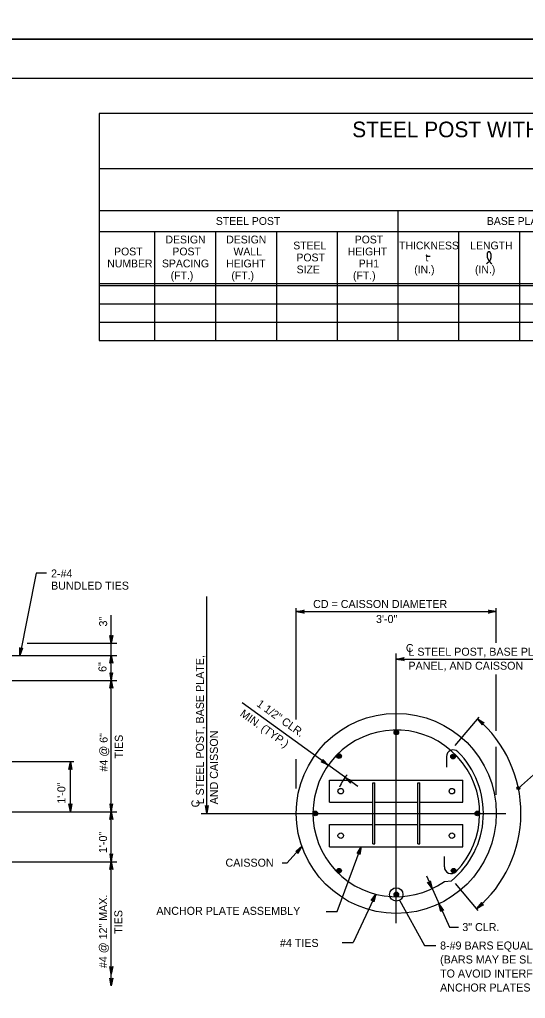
# Model space of a CAD drawing. Extents: x 3475 to 6558, y -3780 to 1166.
# Drawn here: x 4064.1 to 4258.3, y -390.6 to -14.8 of the extents above; entities that cross this region are included whole.
import ezdxf

# ---------------------------------------------------------------- set-up
doc = ezdxf.new("R2010")
doc.units = 0
for name, color, linetype in [('1', 7, 'Continuous'), ('2', 7, 'Continuous'), ('PLT-BNDY', 7, 'Continuous')]:
    doc.layers.add(name, color=color, linetype=linetype)

msp = doc.modelspace()

# ---------------------------------------------------------------- linework, layer by layer
at = {"layer": '1'}
for p, q in [((4094.64, -50.81), (4094.64, -138.01)), ((4574.64, -50.81), (4094.64, -50.81)), ((4574.64, -72.14), (4094.64, -72.14)), ((4094.64, -88.14), (4574.64, -88.14)), ((4094.64, -88.14), (4205.97, -88.14)), ((4209.3, -88.14), (4209.3, -138.01)), ((4094.64, -96.14), (4574.64, -96.14)), ((4115.97, -138.01), (4115.97, -96.14)), ((4139.3, -96.14), (4139.3, -138.01)), ((4162.64, -96.14), (4162.64, -138.01)), ((4185.97, -96.14), (4185.97, -138.01)), ((4232.64, -96.14), (4232.64, -138.01)), ((4255.97, -96.14), (4255.97, -138.01)), ((4220.17, -105.64), (4221.76, -105.64)), ((4094.64, -116.14), (4574.64, -116.14)), ((4094.64, -116.89), (4574.64, -116.89)), ((4094.64, -123.93), (4574.64, -123.93)), ((4094.64, -130.97), (4574.64, -130.97)), ((4094.64, -138.01), (4574.64, -138.01)), ((4070.42, -227.39), (4064.1, -258.93)), ((4074.37, -227.39), (4070.42, -227.39)), ((4135.94, -319.55), (4135.94, -236.27)), ((4099.26, -385.81), (4099.26, -243.47)), ((4170.3, -283.55), (4170.3, -240.78)), ((4170.3, -242.1), (4247.1, -242.1)), ((4247.1, -254.1), (4247.1, -240.78)), ((4067, -254.2), (4101.4, -254.2)), ((3993.38, -258.93), (4101.4, -258.93)), ((4208.7, -361.75), (4208.7, -258.14)), ((4208.7, -260.31), (4288.8, -260.31)), ((4247.1, -287.87), (4247.1, -266.24)), ((3993.38, -268.53), (4101.4, -268.53)), ((4193.88, -309.25), (4149.55, -277.14)), ((4240.44, -282.56), (4231.11, -293.43)), ((4247.1, -312.42), (4247.1, -294)), ((4084.88, -299.7), (3982.86, -299.7)), ((4083.55, -318.9), (4083.55, -299.7)), ((4170.3, -309.97), (4170.3, -298.78)), ((4227.94, -297.78), (4227.95, -301.81)), ((4184.02, -302.11), (4184.02, -302.11)), ((4184.02, -302.11), (4184.02, -302.11)), ((4184.02, -302.11), (4184.02, -302.11)), ((4263.68, -302.73), (4255.56, -309.87)), ((4183.1, -306.75), (4234.3, -306.75)), ((4183.1, -315.29), (4183.1, -306.75)), ((4199.65, -331.29), (4199.65, -307.82)), ((4199.65, -307.82), (4200.45, -307.82)), ((4200.45, -331.29), (4200.45, -307.82)), ((4216.96, -307.82), (4217.75, -307.82)), ((4216.96, -315.09), (4216.96, -307.82)), ((4217.75, -331.29), (4217.75, -307.82)), ((4234.3, -315.29), (4234.3, -306.75)), ((4183.1, -315.29), (4199.65, -315.29)), ((4200.45, -315.29), (4216.96, -315.29)), ((4216.96, -331.29), (4216.96, -315.22)), ((4217.75, -315.29), (4234.3, -315.29)), ((3993.38, -318.9), (4101.4, -318.9)), ((4133.8, -319.55), (4250.71, -319.55)), ((4183.1, -332.35), (4183.1, -323.82)), ((4183.1, -323.82), (4199.65, -323.82)), ((4200.45, -323.82), (4216.96, -323.82)), ((4217.75, -323.82), (4234.3, -323.82)), ((4234.3, -332.35), (4234.3, -323.82)), ((4166.82, -338.5), (4172.48, -332.31)), ((4183.1, -332.35), (4234.3, -332.35)), ((4185.95, -357.28), (4195.22, -332.35)), ((4199.65, -331.29), (4200.45, -331.29)), ((4216.96, -331.29), (4217.75, -331.29)), ((3993.38, -338.1), (4101.4, -338.1)), ((4227.14, -340.09), (4227.15, -336.06)), ((4164.89, -338.5), (4166.82, -338.5)), ((4220.27, -343.57), (4229.08, -363.2)), ((4227.22, -345.65), (4229.87, -345.44)), ((4240.11, -356.77), (4231.37, -346.42)), ((4200.87, -350.58), (4192.13, -369.1)), ((4209.94, -352.9), (4219.58, -370.25)), ((4181.71, -357.28), (4185.95, -357.28)), ((4229.08, -363.2), (4232.55, -363.2)), ((4187.89, -369.1), (4192.13, -369.1)), ((4219.58, -370.25), (4223.82, -370.25))]:
    msp.add_line(p, q, dxfattribs=at)
for points in [[(4170.3, -242.1), (4173.28, -241.54), (4173.05, -241.7), (4172.93, -241.9), (4172.9, -242.1), (4172.93, -242.3), (4173.05, -242.5), (4173.28, -242.66), (4170.3, -242.1), (4173.05, -242.5), (4172.93, -242.3), (4170.3, -242.1), (4172.9, -242.1), (4172.93, -241.9), (4170.3, -242.1), (4173.05, -241.7)], [(4247.1, -242.1), (4244.12, -242.66), (4244.35, -242.5), (4244.47, -242.3), (4244.5, -242.1), (4244.47, -241.9), (4244.35, -241.7), (4244.12, -241.54), (4247.1, -242.1), (4244.35, -241.7), (4244.47, -241.9), (4247.1, -242.1), (4244.5, -242.1), (4244.47, -242.3), (4247.1, -242.1), (4244.35, -242.5)], [(4099.26, -254.2), (4098.7, -251.22), (4098.78, -251.34), (4098.86, -251.45), (4098.96, -251.51), (4099.06, -251.57), (4099.16, -251.59), (4099.26, -251.6), (4099.36, -251.59), (4099.46, -251.57), (4099.56, -251.51), (4099.66, -251.45), (4099.74, -251.34), (4099.82, -251.22), (4099.26, -254.2), (4099.74, -251.34), (4099.66, -251.45), (4099.26, -254.2), (4099.56, -251.51), (4099.46, -251.57), (4099.26, -254.2), (4099.36, -251.59), (4099.26, -251.6), (4099.26, -254.2), (4099.16, -251.59), (4099.06, -251.57), (4099.26, -254.2), (4098.96, -251.51), (4098.86, -251.45), (4099.26, -254.2), (4098.78, -251.34)], [(4064.1, -258.93), (4064.14, -255.9), (4064.2, -256.03), (4064.25, -256.15), (4064.34, -256.23), (4064.43, -256.31), (4064.52, -256.35), (4064.61, -256.38), (4064.72, -256.39), (4064.82, -256.39), (4064.93, -256.35), (4065.04, -256.31), (4065.14, -256.21), (4065.24, -256.12), (4064.1, -258.93), (4065.14, -256.21), (4065.04, -256.31), (4064.1, -258.93), (4064.93, -256.35), (4064.82, -256.39), (4064.1, -258.93), (4064.72, -256.39), (4064.61, -256.38), (4064.1, -258.93), (4064.52, -256.35), (4064.43, -256.31), (4064.1, -258.93), (4064.34, -256.23), (4064.25, -256.15), (4064.1, -258.93), (4064.2, -256.03)], [(4099.26, -258.93), (4099.82, -261.91), (4099.74, -261.8), (4099.66, -261.68), (4099.56, -261.63), (4099.46, -261.57), (4099.36, -261.55), (4099.26, -261.53), (4099.16, -261.55), (4099.06, -261.57), (4098.96, -261.63), (4098.86, -261.68), (4098.78, -261.8), (4098.7, -261.91), (4099.26, -258.93), (4098.78, -261.8), (4098.86, -261.68), (4099.26, -258.93), (4098.96, -261.63), (4099.06, -261.57), (4099.26, -258.93), (4099.16, -261.55), (4099.26, -261.53), (4099.26, -258.93), (4099.36, -261.55), (4099.46, -261.57), (4099.26, -258.93), (4099.56, -261.63), (4099.66, -261.68), (4099.26, -258.93), (4099.74, -261.8)], [(4208.7, -260.31), (4211.68, -259.75), (4211.45, -259.91), (4211.34, -260.11), (4211.3, -260.31), (4211.34, -260.51), (4211.45, -260.71), (4211.68, -260.87), (4208.7, -260.31), (4211.45, -260.71), (4211.34, -260.51), (4208.7, -260.31), (4211.3, -260.31), (4211.34, -260.11), (4208.7, -260.31), (4211.45, -259.91)], [(4099.26, -268.53), (4099.82, -265.55), (4099.74, -265.66), (4099.66, -265.78), (4099.56, -265.84), (4099.46, -265.9), (4099.36, -265.91), (4099.26, -265.93), (4099.16, -265.91), (4099.06, -265.9), (4098.96, -265.84), (4098.86, -265.78), (4098.78, -265.66), (4098.7, -265.55), (4099.26, -268.53), (4098.78, -265.66), (4098.86, -265.78), (4099.26, -268.53), (4098.96, -265.84), (4099.06, -265.9), (4099.26, -268.53), (4099.16, -265.91), (4099.26, -265.93), (4099.26, -268.53), (4099.36, -265.91), (4099.46, -265.9), (4099.26, -268.53), (4099.56, -265.84), (4099.66, -265.78), (4099.26, -268.53), (4099.74, -265.66)], [(4099.26, -268.53), (4099.82, -271.51), (4099.74, -271.4), (4099.66, -271.28), (4099.56, -271.23), (4099.46, -271.17), (4099.36, -271.15), (4099.26, -271.13), (4099.16, -271.15), (4099.06, -271.17), (4098.96, -271.23), (4098.86, -271.28), (4098.78, -271.4), (4098.7, -271.51), (4099.26, -268.53), (4098.78, -271.4), (4098.86, -271.28), (4099.26, -268.53), (4098.96, -271.23), (4099.06, -271.17), (4099.26, -268.53), (4099.16, -271.15), (4099.26, -271.13), (4099.26, -268.53), (4099.36, -271.15), (4099.46, -271.17), (4099.26, -268.53), (4099.56, -271.23), (4099.66, -271.28), (4099.26, -268.53), (4099.74, -271.4)], [(4239.85, -283.24), (4242.48, -284.76), (4242.2, -284.73), (4241.98, -284.8), (4241.83, -284.93), (4241.72, -285.11), (4241.68, -285.34), (4241.75, -285.61), (4239.85, -283.24), (4241.68, -285.34), (4241.72, -285.11), (4239.85, -283.24), (4241.83, -284.93), (4241.98, -284.8), (4239.85, -283.24), (4242.2, -284.73)], [(4083.55, -299.7), (4084.11, -302.68), (4084.03, -302.57), (4083.95, -302.45), (4083.85, -302.39), (4083.75, -302.34), (4083.65, -302.32), (4083.55, -302.3), (4083.45, -302.32), (4083.35, -302.34), (4083.25, -302.39), (4083.15, -302.45), (4083.07, -302.57), (4082.99, -302.68), (4083.55, -299.7), (4083.07, -302.57), (4083.15, -302.45), (4083.55, -299.7), (4083.25, -302.39), (4083.35, -302.34), (4083.55, -299.7), (4083.45, -302.32), (4083.55, -302.3), (4083.55, -299.7), (4083.65, -302.32), (4083.75, -302.34), (4083.55, -299.7), (4083.85, -302.39), (4083.95, -302.45), (4083.55, -299.7), (4084.03, -302.57)], [(4182.58, -301.07), (4179.84, -299.77), (4180.12, -299.77), (4180.33, -299.68), (4180.47, -299.54), (4180.56, -299.36), (4180.59, -299.13), (4180.49, -298.86), (4182.58, -301.07), (4180.59, -299.13), (4180.56, -299.36), (4182.58, -301.07), (4180.47, -299.54), (4180.33, -299.68), (4182.58, -301.07), (4180.12, -299.77)], [(4189.03, -305.74), (4191.77, -307.03), (4191.49, -307.03), (4191.28, -307.12), (4191.13, -307.26), (4191.04, -307.44), (4191.02, -307.67), (4191.12, -307.94), (4189.03, -305.74), (4191.02, -307.67), (4191.04, -307.44), (4189.03, -305.74), (4191.13, -307.26), (4191.28, -307.12), (4189.03, -305.74), (4191.49, -307.03)], [(4083.55, -318.9), (4082.99, -315.92), (4083.07, -316.03), (4083.15, -316.15), (4083.25, -316.21), (4083.35, -316.27), (4083.45, -316.28), (4083.55, -316.3), (4083.65, -316.28), (4083.75, -316.27), (4083.85, -316.21), (4083.95, -316.15), (4084.03, -316.03), (4084.11, -315.92), (4083.55, -318.9), (4084.03, -316.03), (4083.95, -316.15), (4083.55, -318.9), (4083.85, -316.21), (4083.75, -316.27), (4083.55, -318.9), (4083.65, -316.28), (4083.55, -316.3), (4083.55, -318.9), (4083.45, -316.28), (4083.35, -316.27), (4083.55, -318.9), (4083.25, -316.21), (4083.15, -316.15), (4083.55, -318.9), (4083.07, -316.03)], [(4099.26, -318.9), (4099.82, -315.92), (4099.74, -316.03), (4099.66, -316.15), (4099.56, -316.21), (4099.46, -316.27), (4099.36, -316.28), (4099.26, -316.3), (4099.16, -316.28), (4099.06, -316.27), (4098.96, -316.21), (4098.86, -316.15), (4098.78, -316.03), (4098.7, -315.92), (4099.26, -318.9), (4098.78, -316.03), (4098.86, -316.15), (4099.26, -318.9), (4098.96, -316.21), (4099.06, -316.27), (4099.26, -318.9), (4099.16, -316.28), (4099.26, -316.3), (4099.26, -318.9), (4099.36, -316.28), (4099.46, -316.27), (4099.26, -318.9), (4099.56, -316.21), (4099.66, -316.15), (4099.26, -318.9), (4099.74, -316.03)], [(4099.26, -318.9), (4099.82, -321.88), (4099.74, -321.77), (4099.66, -321.65), (4099.56, -321.59), (4099.46, -321.54), (4099.36, -321.52), (4099.26, -321.5), (4099.16, -321.52), (4099.06, -321.54), (4098.96, -321.59), (4098.86, -321.65), (4098.78, -321.77), (4098.7, -321.88), (4099.26, -318.9), (4098.78, -321.77), (4098.86, -321.65), (4099.26, -318.9), (4098.96, -321.59), (4099.06, -321.54), (4099.26, -318.9), (4099.16, -321.52), (4099.26, -321.5), (4099.26, -318.9), (4099.36, -321.52), (4099.46, -321.54), (4099.26, -318.9), (4099.56, -321.59), (4099.66, -321.65), (4099.26, -318.9), (4099.74, -321.77)], [(4135.94, -319.55), (4135.38, -316.57), (4135.54, -316.8), (4135.74, -316.92), (4135.94, -316.95), (4136.14, -316.92), (4136.34, -316.8), (4136.5, -316.57), (4135.94, -319.55), (4136.34, -316.8), (4136.14, -316.92), (4135.94, -319.55), (4135.94, -316.95), (4135.74, -316.92), (4135.94, -319.55), (4135.54, -316.8)], [(4172.48, -332.31), (4170.88, -334.89), (4170.92, -334.61), (4170.85, -334.39), (4170.73, -334.23), (4170.56, -334.12), (4170.33, -334.07), (4170.06, -334.13), (4172.48, -332.31), (4170.33, -334.07), (4170.56, -334.12), (4172.48, -332.31), (4170.73, -334.23), (4170.85, -334.39), (4172.48, -332.31), (4170.92, -334.61)], [(4195.22, -332.35), (4194.71, -335.34), (4194.67, -335.21), (4194.64, -335.07), (4194.56, -334.98), (4194.49, -334.89), (4194.4, -334.84), (4194.32, -334.79), (4194.22, -334.77), (4194.12, -334.75), (4194, -334.77), (4193.89, -334.79), (4193.77, -334.87), (4193.66, -334.95), (4195.22, -332.35), (4193.77, -334.87), (4193.89, -334.79), (4195.22, -332.35), (4194, -334.77), (4194.12, -334.75), (4195.22, -332.35), (4194.22, -334.77), (4194.32, -334.79), (4195.22, -332.35), (4194.4, -334.84), (4194.49, -334.89), (4195.22, -332.35), (4194.56, -334.98), (4194.64, -335.07), (4195.22, -332.35), (4194.67, -335.21)], [(4099.26, -338.1), (4099.82, -335.12), (4099.74, -335.23), (4099.66, -335.35), (4099.56, -335.41), (4099.46, -335.47), (4099.36, -335.48), (4099.26, -335.5), (4099.16, -335.48), (4099.06, -335.47), (4098.96, -335.41), (4098.86, -335.35), (4098.78, -335.23), (4098.7, -335.12), (4099.26, -338.1), (4098.78, -335.23), (4098.86, -335.35), (4099.26, -338.1), (4098.96, -335.41), (4099.06, -335.47), (4099.26, -338.1), (4099.16, -335.48), (4099.26, -335.5), (4099.26, -338.1), (4099.36, -335.48), (4099.46, -335.47), (4099.26, -338.1), (4099.56, -335.41), (4099.66, -335.35), (4099.26, -338.1), (4099.74, -335.23)], [(4099.26, -338.1), (4099.82, -341.08), (4099.74, -340.97), (4099.66, -340.85), (4099.56, -340.8), (4099.46, -340.74), (4099.36, -340.72), (4099.26, -340.7), (4099.16, -340.72), (4099.06, -340.74), (4098.96, -340.8), (4098.86, -340.85), (4098.78, -340.97), (4098.7, -341.08), (4099.26, -338.1), (4098.78, -340.97), (4098.86, -340.85), (4099.26, -338.1), (4098.96, -340.8), (4099.06, -340.74), (4099.26, -338.1), (4099.16, -340.72), (4099.26, -340.7), (4099.26, -338.1), (4099.36, -340.72), (4099.46, -340.74), (4099.26, -338.1), (4099.56, -340.8), (4099.66, -340.85), (4099.26, -338.1), (4099.74, -340.97)], [(4222.46, -348.45), (4220.73, -345.95), (4220.97, -346.1), (4221.2, -346.13), (4221.4, -346.07), (4221.56, -345.96), (4221.7, -345.77), (4221.75, -345.5), (4222.46, -348.45), (4221.7, -345.77), (4221.56, -345.96), (4222.46, -348.45), (4221.4, -346.07), (4221.2, -346.13), (4222.46, -348.45), (4220.97, -346.1)], [(4200.87, -350.58), (4200.1, -353.52), (4200.06, -353.24), (4199.93, -353.05), (4199.76, -352.93), (4199.57, -352.88), (4199.33, -352.9), (4199.09, -353.04), (4200.87, -350.58), (4199.33, -352.9), (4199.57, -352.88), (4200.87, -350.58), (4199.76, -352.93), (4199.93, -353.05), (4200.87, -350.58), (4200.06, -353.24)], [(4225.08, -354.29), (4226.81, -356.78), (4226.57, -356.63), (4226.34, -356.61), (4226.15, -356.66), (4225.98, -356.77), (4225.84, -356.96), (4225.79, -357.24), (4225.08, -354.29), (4225.84, -356.96), (4225.98, -356.77), (4225.08, -354.29), (4226.15, -356.66), (4226.34, -356.61), (4225.08, -354.29), (4226.57, -356.63)], [(4239.56, -356.12), (4241.48, -353.76), (4241.41, -354.03), (4241.45, -354.26), (4241.55, -354.44), (4241.7, -354.57), (4241.92, -354.65), (4242.2, -354.62), (4239.56, -356.12), (4241.92, -354.65), (4241.7, -354.57), (4239.56, -356.12), (4241.55, -354.44), (4241.45, -354.26), (4239.56, -356.12), (4241.41, -354.03)], [(4099.26, -381.33), (4098.7, -378.35), (4098.86, -378.58), (4099.06, -378.7), (4099.26, -378.73), (4099.46, -378.7), (4099.66, -378.58), (4099.82, -378.35), (4099.26, -381.33), (4099.66, -378.58), (4099.46, -378.7), (4099.26, -381.33), (4099.26, -378.73), (4099.06, -378.7), (4099.26, -381.33), (4098.86, -378.58)], [(4099.26, -385.81), (4098.7, -382.83), (4098.86, -383.06), (4099.06, -383.17), (4099.26, -383.21), (4099.46, -383.17), (4099.66, -383.06), (4099.82, -382.83), (4099.26, -385.81), (4099.66, -383.06), (4099.46, -383.17), (4099.26, -385.81), (4099.26, -383.21), (4099.06, -383.17), (4099.26, -385.81), (4098.86, -383.06)]]:
    msp.add_lwpolyline(points, dxfattribs=at)
for centre, radius in [((4208.7, -319.55), 38.4), ((4208.7, -288.45), 0.885), ((4208.7, -288.45), 0.669), ((4208.7, -288.45), 0.479), ((4208.7, -288.45), 0.271), ((4186.71, -297.56), 0.885), ((4230.49, -297.73), 0.885), ((4186.71, -297.56), 0.669), ((4186.71, -297.56), 0.479), ((4186.71, -297.56), 0.271), ((4230.49, -297.73), 0.669), ((4230.49, -297.73), 0.479), ((4230.49, -297.73), 0.271), ((4187.37, -311.02), 1.06), ((4230.04, -311.02), 1.06), ((4255.56, -309.87), 0.533), ((4255.56, -309.87), 0.267), ((4177.6, -319.55), 0.885), ((4177.6, -319.55), 0.669), ((4177.6, -319.55), 0.479), ((4177.6, -319.55), 0.271), ((4239.81, -319.55), 0.885), ((4239.81, -319.55), 0.669), ((4239.81, -319.55), 0.479), ((4239.81, -319.55), 0.271), ((4187.37, -328.09), 1.06), ((4230.04, -328.09), 1.06), ((4186.71, -341.55), 0.885), ((4186.71, -341.55), 0.669), ((4186.71, -341.55), 0.479), ((4186.71, -341.55), 0.271), ((4230.7, -341.55), 0.885), ((4230.7, -341.55), 0.669), ((4230.7, -341.55), 0.479), ((4230.7, -341.55), 0.271), ((4208.7, -350.66), 2.56), ((4208.7, -350.66), 0.885), ((4208.7, -350.66), 0.669), ((4208.7, -350.66), 0.479), ((4208.7, -350.66), 0.271)]:
    msp.add_circle(centre, radius, dxfattribs=at)
for centre, radius, start, end in [((4208.7, -319.55), 47.85, 310.1655, 49.3728), ((4208.7, -319.55), 32, 315.5847, 305.3578), ((4230.55, -297.79), 2.61, 45.958, 179.6395), ((4208.7, -319.55), 33.44, 309.2717, 44.9704), ((4208.7, -319.55), 24.04, 141.8273, 155.2097), ((4229.75, -340.07), 2.61, 180.3605, 314.042)]:
    msp.add_arc(centre, radius, start, end, dxfattribs=at)
msp.add_spline([(4243.36, -108.55), (4243.57, -108.39), (4243.69, -108.25), (4243.89, -108.06), (4244.05, -107.89), (4244.33, -107.68), (4244.53, -107.43), (4244.71, -107.23), (4244.83, -107), (4244.93, -106.75), (4245.01, -106.52), (4245.09, -106.29), (4245.12, -106.09), (4245.15, -105.84), (4245.17, -105.62), (4245.15, -105.38), (4245.11, -105.13), (4245.06, -104.88), (4245, -104.65), (4244.91, -104.43), (4244.84, -104.29), (4244.74, -104.19), (4244.65, -104.1), (4244.55, -104.01), (4244.44, -103.95), (4244.35, -103.93), (4244.19, -103.93), (4244.09, -103.95), (4243.94, -104), (4243.85, -104.08), (4243.79, -104.17), (4243.72, -104.29), (4243.65, -104.4), (4243.61, -104.55), (4243.58, -104.65), (4243.54, -104.89), (4243.52, -105.06), (4243.54, -105.26), (4243.54, -105.45), (4243.58, -105.73), (4243.6, -105.96), (4243.64, -106.13), (4243.71, -106.35), (4243.81, -106.58), (4243.91, -106.77), (4244, -106.97), (4244.12, -107.2), (4244.32, -107.38), (4244.44, -107.59), (4244.57, -107.74), (4244.68, -107.92), (4244.83, -108.09), (4244.96, -108.27), (4245.07, -108.37), (4245.18, -108.51), (4245.29, -108.67)], degree=3, dxfattribs=at)
at = {"layer": '2'}
msp.add_line((3801.34, -37.31), (4587.34, -37.31), dxfattribs=at)
at = {"layer": 'PLT-BNDY'}
for points in [[(3761.34, 571.69), (4602.34, 571.69), (4602.34, -22.31), (3761.34, -22.31)], [(3761.34, -22.31), (4602.34, -22.31), (4602.34, -616.31), (3761.34, -616.31)]]:
    msp.add_lwpolyline(points, close=True, dxfattribs=at)

# ---------------------------------------------------------------- texts
at = {"layer": '1'}
for s, height, p in [('STEEL POST WITH BASE PLATE CONNECTION TO CAISSON', 6.0001, (4191.77, -59.98)), ('STEEL POST', 3, (4139.41, -93.64)), ('BASE PLATE', 3, (4243.47, -93.64)), ('DESIGN', 3, (4120.08, -100.74)), ('DESIGN', 3, (4143.41, -100.74)), ('POST', 3, (4192.73, -100.74)), ('STEEL', 3, (4169.14, -103.04)), ('THICKNESS', 3, (4209.77, -103.04)), ('LENGTH', 3, (4237.07, -103.04)), ('POST', 3, (4100.36, -105.34)), ('POST', 3, (4122.73, -105.34)), ('WALL', 3, (4146.19, -105.34)), ('POST', 3, (4170.36, -107.64)), ('HEIGHT', 3, (4190.03, -105.34)), ('t', 3, (4219.88, -107.64)), ('NUMBER', 3, (4097.71, -109.94)), ('SPACING', 3, (4118.73, -109.94)), ('HEIGHT', 3, (4143.36, -109.94)), ('PH1', 3, (4194.27, -109.94)), ('(FT.)', 3, (4122.06, -114.54)), ('(FT.)', 3, (4145.39, -114.54)), ('SIZE', 3, (4170.43, -112.24)), ('(FT.)', 3, (4192.06, -114.54)), ('(IN.)', 3, (4215.57, -112.24)), ('(IN.)', 3, (4238.9, -112.24)), ('2-#4', 3.072, (4076.14, -228.99)), ('BUNDLED TIES', 3.072, (4076.14, -233.66)), ('CD = CAISSON DIAMETER', 3.072, (4176.76, -240.7)), ('3\'-0"', 3.072, (4200.91, -246.46)), ('C', 3, (4212.38, -257.55)), ('L STEEL POST, BASE PLATE,', 3.072, (4213.35, -259.03)), ('PANEL, AND CAISSON', 3.072, (4213.35, -264.4)), ('CAISSON', 3.072, (4143.12, -340.01)), ('ANCHOR PLATE ASSEMBLY', 3.072, (4116.58, -358.5)), ('3" CLR.', 3.072, (4234.04, -364.73)), ('#4 TIES', 3.072, (4164.03, -370.82)), ('8-#9 BARS EQUALLY SPACED', 3.072, (4225.51, -371.81)), ('(BARS MAY BE SLIGHTLY ADJUSTED', 3.072, (4225.51, -377.18)), ('TO AVOID INTERFERENCE WITH ', 3.072, (4225.51, -382.56)), ('ANCHOR PLATES AND ANCHOR BOLTS)', 3.072, (4225.51, -387.94))]:
    msp.add_text(s, height=height, dxfattribs=at).set_placement(p)
for s, height, rotation, p in [('3"', 3.072, 90, (4097.68, -247.82)), ('L STEEL POST, BASE PLATE,', 3.072, 90, (4134.82, -316.08)), ('6"', 3.072, 90, (4097.42, -265.24)), ('1 1/2" CLR.', 3.072, 324.4593, (4154.8, -278.13)), ('MIN. (TYP.)', 3.072, 324.4593, (4148.43, -281.89)), ('#4 @ 6"', 3.072, 90, (4097.86, -303.48)), ('AND CAISSON', 3.072, 90, (4140.2, -316.08)), ('TIES', 3.072, 90, (4103.7, -298.48)), ('1\'-0"', 3.072, 90, (4081.64, -315.85)), ('C', 3.07, 90, (4133.12, -317.25)), ('1\'-0"', 3.072, 90, (4097.61, -334.79)), ('#4 @ 12" MAX.', 3.072, 90, (4097.68, -378.95)), ('TIES', 3.072, 90, (4103.51, -365.8))]:
    msp.add_text(s, height=height, rotation=rotation, dxfattribs=at).set_placement(p)

doc.saveas('drawing.dxf')
